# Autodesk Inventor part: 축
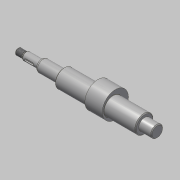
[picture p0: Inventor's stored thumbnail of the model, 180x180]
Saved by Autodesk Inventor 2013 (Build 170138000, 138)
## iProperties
Created: 2015-12
Part Number: 축
Document SubType Name: Modeling
Designer: mdu
Density: 7.86 g/cm^3
Material: 강철, 연강
Mass: 484.681 g
Surface Area: 125.968 cm^2
Volume: 61.6642 cm^3
Author: mdu
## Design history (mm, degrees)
sketch "스케치1"
  geometry: L1 (62, 100.9)-(62, 67.1) reference; L2 (51, 101.2)-(51, 84) reference; L3 (-51, 84)-(-51, 101.2) reference; L4 (-62, 67.1)-(-62, 100.9) reference; L5 (-51.6, 91.5)-(-61.4, 91.5) reference; L6 (51.6, 91.5)-(61.4, 91.5) reference; L7 (67, 84)-(-109, 84); L8 (-77, 64.201)-(-77, 103.799) reference; L9 (67, 84)-(67, 91.5); L10 (67, 91.5)-(51, 91.5); L11 (51, 91.5)-(51, 95.5); L12 (51, 95.5)-(-51, 95.5); L13 (-51, 95.5)-(-51, 91.5); L14 (-51, 91.5)-(-79, 91.5); L15 (-79, 91.5)-(-79, 89); L16 (-79, 89)-(-99, 89); L17 (-99, 89)-(-99, 87); L18 (-100.5, 88)-(-109, 88); L19 (-109, 88)-(-109, 84); L20 (-99, 87)-(-100.5, 87); L21 (-100.5, 87)-(-100.5, 88); 2 further points
  constraints: 32 end point, 7 parallel, 6 point on line, 5 perpendicular, 2 collinear, 2 horizontal, 1 midpoint, 4 other
  dimensions: "d0" = 5 distance from line of L7.start L1; "d2" = 2 distance between parallel lines of L15 L8; "d3" = 23 diameter of L12 L7; "d4" = 10 diameter of L16 L7; "d5" = 1.5 distance of L17.end L20.end; "d6" = 6 diameter of L20 L7; "d7" = 20 distance of L15.end L16.end; "d8" = 10 distance between parallel lines of L17 L19; "d9" = 8 diameter of L18 L7
revolve "회전1" sketch "스케치1" stored, may be unused: angle "d10" = 90 deg
sketch "스케치2"
  geometry: C1 r 11.5 at (84, 0) reference; C2 r 11.5 at (84, 0) reference; C3 r 16.5 at (87, 0); 1 further point
  constraints: 1 centre point, 1 horizontal alignment
  dimensions: "d11" = 33 diameter of C3; "d12" = 3 distance of C3.centre C1.centre
extrude "돌출1" join sketch "스케치2" stored distance "d13" = 22; taper "d14" = 0 deg
chamfer "모따기1" distance "d15" = 1; stored, may be unused: second distance "d16" = 2, angle "d17" = 45 deg
feature "스레드1" dims "d18" = 10, "d19" = 0
node "작업 평면1"
sketch "스케치3"
  geometry: L1 (-5.5, -1.5)-(3.5, -1.5); L2 (3.5, 1.5)-(-5.5, 1.5); L3 (-10, -4)-(-10, 4) reference; A1 r 1.5 centre (3.5, 0) between (3.5, -1.5) and (3.5, 1.5); A2 r 1.5 centre (-5.5, 0) between (-5.5, 1.5) and (-5.5, -1.5); 2 further points
  constraints: 4 end point, 4 point on circle, 4 tangent, 2 centre point, 1 horizontal, 1 horizontal alignment, 1 midpoint, 1 parallel
  dimensions: "d20" = 3 distance between parallel lines of L1 L2; "d21" = 12 dimension on A1 A2; "d22" = 3 distance edge to line of A2 L3
extrude "돌출2" cut sketch "스케치3" distance "d23" = 1.8; taper "d24" = 0 deg
fillet "모깎기1" dims "d25" = 0.3
fillet "모깎기2" dims "d26" = 3
node "솔리드1"
node "참조1"
node "참조2"
node "참조3"
node "참조4"
node "참조5"
node "투영된 루프1"
